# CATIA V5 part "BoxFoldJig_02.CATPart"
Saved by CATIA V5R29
Part number: BoxFoldJig_02
Source: Unknown
Bounding box of the stored display mesh (mm): x -128.606 to 128.606, y -217.253 to 131.984, z 141.34 to 260
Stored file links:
  C:\가치같이\SmartFactory_BoxErectorConveyor\Boxing(over)\BoxFoldJig_02.CATPart
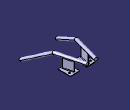
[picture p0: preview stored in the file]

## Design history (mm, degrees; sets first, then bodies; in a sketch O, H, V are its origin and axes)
Body1 "PartBody.1" (main body)
  Solid1: solid without history
Body2 "PartBody.2"
  Solid2: solid without history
